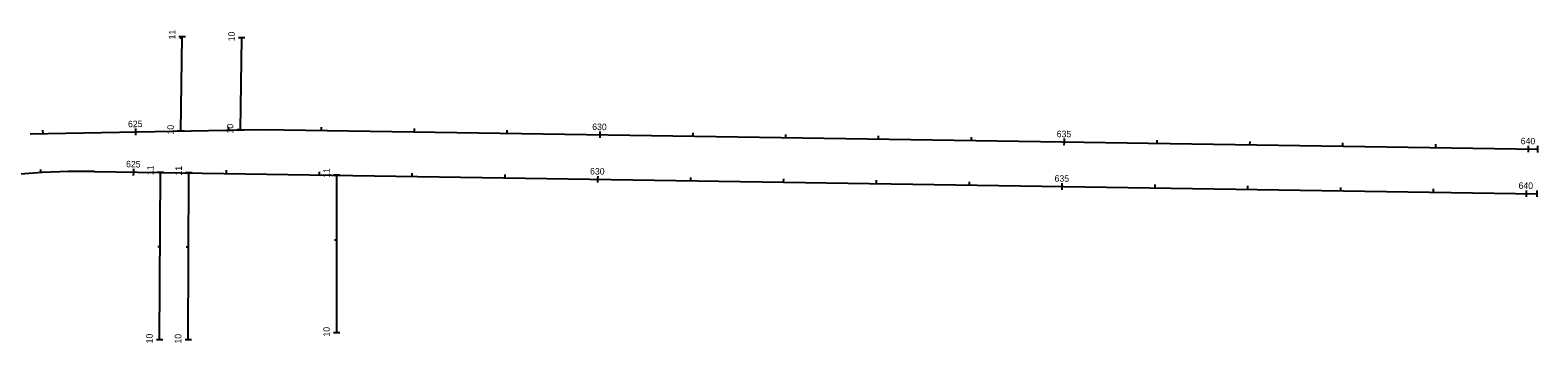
# Model space of a CAD drawing. Extents: x 596007 to 607538, y 326212 to 405053.
# Drawn here: x 604538 to 606161, y 349721 to 350058 of the extents above; entities that cross this region are included whole.
import ezdxf

# ---------------------------------------------------------------- set-up
doc = ezdxf.new("R2010")
doc.units = 0
for name, color, linetype in [('P_ALI', 7, 'Continuous'), ('P_ALI_200_Sta', 7, 'Continuous'), ('P_ALI_200_Tic', 7, 'Continuous')]:
    doc.layers.add(name, color=color, linetype=linetype)

msp = doc.modelspace()

# ---------------------------------------------------------------- linework, layer by layer
at = {"layer": 'P_ALI'}
for points in [[(604700.1, 349948.9), (604701.6, 350050.3)], [(604764.2, 349950.1), (604765.7, 350049.3)], [(604537.9, 349946), (604787.8, 349950.5)], [(604787.8, 349950.5), (606161.4, 349929.4)], [(604607.3, 349905.3), (606160.7, 349881.4)], [(604677.3, 349724), (604678.2, 349904.2)], [(604708.2, 349723.9), (604708.7, 349903.7)], [(604868, 349731.3), (604868, 349901.3)]]:
    msp.add_lwpolyline(points, dxfattribs=at)
msp.add_arc((604595, 349105.4), 800, 89.1186, 99.8942, dxfattribs=at)
at = {"layer": 'P_ALI_200_Sta'}
for points in [[(604701.6, 350050.3), (604698.1, 350050.4)], [(604701.6, 350050.3), (604701.6, 350050.3)], [(604705.1, 350050.3), (604701.6, 350050.3)], [(604765.7, 350049.3), (604762.2, 350049.4)], [(604765.7, 350049.3), (604765.7, 350049.3)], [(604769.2, 350049.3), (604765.7, 350049.3)], [(604551.7, 349946.3), (604551.6, 349949.8)], [(604651.7, 349948.1), (604651.6, 349951.6)], [(604651.7, 349948.1), (604651.7, 349948.1)], [(604651.7, 349944.6), (604651.7, 349948.1)], [(604700.1, 349948.9), (604696.6, 349949)], [(604700.1, 349948.9), (604700.1, 349948.9)], [(604703.6, 349948.9), (604700.1, 349948.9)], [(604751.7, 349949.9), (604751.6, 349953.4)], [(604764.2, 349950.1), (604760.7, 349950.1)], [(604764.2, 349950.1), (604764.2, 349950.1)], [(604767.7, 349950), (604764.2, 349950.1)], [(604851.7, 349949.5), (604851.7, 349953)], [(604951.6, 349948), (604951.7, 349951.5)], [(605051.6, 349946.4), (605051.7, 349949.9)], [(605151.6, 349944.9), (605151.7, 349948.4)], [(605151.6, 349944.9), (605151.6, 349944.9)], [(605151.6, 349941.4), (605151.6, 349944.9)], [(605251.6, 349943.4), (605251.7, 349946.9)], [(605351.6, 349941.8), (605351.6, 349945.3)], [(605451.6, 349940.3), (605451.6, 349943.8)], [(605551.6, 349938.7), (605551.6, 349942.2)], [(605651.5, 349933.7), (605651.6, 349937.2)], [(605651.6, 349937.2), (605651.6, 349940.7)], [(605651.6, 349937.2), (605651.6, 349937.2)], [(605751.5, 349935.7), (605751.6, 349939.2)], [(605851.5, 349934.1), (605851.6, 349937.6)], [(605951.5, 349932.6), (605951.6, 349936.1)], [(606051.5, 349931.1), (606051.6, 349934.6)], [(606151.4, 349926), (606151.5, 349929.5)], [(606151.5, 349929.5), (606151.6, 349933)], [(606151.5, 349929.5), (606151.5, 349929.5)], [(606161.4, 349929.4), (606161.5, 349932.9)], [(606161.4, 349929.4), (606161.4, 349929.4)], [(606161.4, 349925.9), (606161.4, 349929.4)], [(604549.4, 349904.1), (604549.2, 349907.6)], [(604649.3, 349901.1), (604649.4, 349904.6)], [(604649.4, 349904.6), (604649.4, 349908.1)], [(604649.4, 349904.6), (604649.4, 349904.6)], [(604678.2, 349904.2), (604674.7, 349904.2)], [(604678.2, 349904.2), (604678.2, 349904.2)], [(604681.7, 349904.2), (604678.2, 349904.2)], [(604708.7, 349903.7), (604705.2, 349903.7)], [(604708.7, 349903.7), (604708.7, 349903.7)], [(604712.2, 349903.7), (604708.7, 349903.7)], [(604749.4, 349903.1), (604749.4, 349906.6)], [(604849.4, 349901.5), (604849.4, 349905)], [(604868, 349901.3), (604864.5, 349901.3)], [(604868, 349901.3), (604868, 349901.3)], [(604871.5, 349901.3), (604868, 349901.3)], [(604949.4, 349900), (604949.4, 349903.5)], [(605049.3, 349898.5), (605049.4, 349902)], [(605149.3, 349896.9), (605149.4, 349900.4)], [(605149.3, 349896.9), (605149.3, 349896.9)], [(605149.3, 349893.4), (605149.3, 349896.9)], [(605249.3, 349895.4), (605249.4, 349898.9)], [(605349.3, 349893.9), (605349.4, 349897.4)], [(605449.3, 349892.3), (605449.4, 349895.8)], [(605549.3, 349890.8), (605549.3, 349894.3)], [(605649.2, 349885.7), (605649.3, 349889.2)], [(605649.3, 349889.2), (605649.3, 349892.7)], [(605649.3, 349889.2), (605649.3, 349889.2)], [(605749.3, 349887.7), (605749.3, 349891.2)], [(605849.3, 349886.2), (605849.3, 349889.7)], [(605949.2, 349884.6), (605949.3, 349888.1)], [(606049.2, 349883.1), (606049.3, 349886.6)], [(606149.2, 349881.5), (606149.3, 349885)], [(606149.2, 349881.5), (606149.2, 349881.5)], [(606149.2, 349878), (606149.2, 349881.5)], [(606160.6, 349877.9), (606160.7, 349881.4)], [(606160.7, 349881.4), (606160.7, 349884.9)], [(606160.7, 349881.4), (606160.7, 349881.4)], [(604677.3, 349724), (604673.8, 349724)], [(604677.3, 349724), (604677.3, 349724)], [(604680.8, 349724), (604677.3, 349724)], [(604708.2, 349723.9), (604704.7, 349723.9)], [(604708.2, 349723.9), (604708.2, 349723.9)], [(604711.7, 349723.9), (604708.2, 349723.9)], [(604868, 349731.3), (604864.5, 349731.3)], [(604868, 349731.3), (604868, 349731.3)], [(604871.5, 349731.3), (604868, 349731.3)]]:
    msp.add_lwpolyline(points, dxfattribs=at)
at = {"layer": 'P_ALI_200_Tic'}
for points in [[(604701.6, 350048.9), (604699.1, 350048.9)], [(604868, 349831.3), (604865.5, 349831.3)], [(604677.8, 349824), (604675.3, 349824)], [(604708.5, 349823.9), (604706, 349823.9)]]:
    msp.add_lwpolyline(points, dxfattribs=at)

# ---------------------------------------------------------------- texts
at = {"layer": 'P_ALI_200_Sta'}
for s, height, rotation, p in [('11', 7, 89.1186, (604694.1, 350047.6)), ('10', 7, 89.1186, (604758.2, 350045.5)), ('625', 7, 1.0298, (604643.3, 349952.9)), ('10', 7, 89.1186, (604692.5, 349945.1)), ('10', 7, 89.1186, (604756.6, 349946.2)), ('630', 7, 359.1186, (605143.1, 349950)), ('635', 7, 359.1186, (605643.3, 349942.3)), ('640', 7, 359.1186, (606143, 349934.7)), ('640', 0.0000000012, 359.1186, (606161.5, 349934.4)), ('625', 7, 359.1186, (604641.1, 349909.8)), ('11', 7, 89.714, (604670.7, 349901.4)), ('11', 7, 89.821, (604701.2, 349900.9)), ('11', 7, 90, (604860.5, 349898.5)), ('630', 7, 359.1186, (605140.8, 349902.1)), ('635', 7, 359.1186, (605641, 349894.4)), ('640', 7, 359.1186, (606140.7, 349886.7)), ('640', 0.0000000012, 359.1186, (606160.8, 349886.4)), ('10', 7, 90, (604860.5, 349727.4)), ('10', 7, 89.714, (604669.8, 349720.1)), ('10', 7, 89.821, (604700.6, 349719.9))]:
    msp.add_text(s, height=height, rotation=rotation, dxfattribs=at).set_placement(p)

doc.saveas('drawing.dxf')
